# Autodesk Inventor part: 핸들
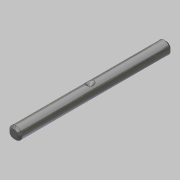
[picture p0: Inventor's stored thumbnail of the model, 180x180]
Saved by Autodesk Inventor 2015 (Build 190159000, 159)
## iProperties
Created: 2019-04
Part Number: 핸들
Material: 스테인리스강
Document SubType Name: Modeling
Designer: mduedu
Density: 1 g/cm^3
Appearance: 반광택
Author: mduedu
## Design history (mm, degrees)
sketch "스케치1"
  geometry: C1 r 3 at (0, 0); 1 further point
  constraints: 1 centre point, 1 coincident
  dimensions: "d0" = 6 diameter of C1
extrude "돌출1" new body sketch "스케치1" stored distance "d1" = 74; taper "d2" = 0 deg
chamfer "모따기1" distance "d3" = 1; stored, may be unused: second distance "d4" = 2, angle "d5" = 45 deg
sketch "스케치2"
  geometry: L1 (-36, 3)-(36, 3) reference; L2 (0, 3)-(0, 1); L3 (0, 1)-(2, 3); L4 (0, 3)-(2, 3); 1 further point
  constraints: 6 end point, 2 perpendicular, 1 midpoint, 1 point on line
  dimensions: "d6" = 4 diameter of L3.end L2; "d8" = 45 deg angle of L3 L2
revolve "회전1" sketch "스케치2" stored, may be unused: angle "d10" = 90 deg
node "작업점1"
  node "작업축1"
  node "작업 평면1"
node "솔리드1"
